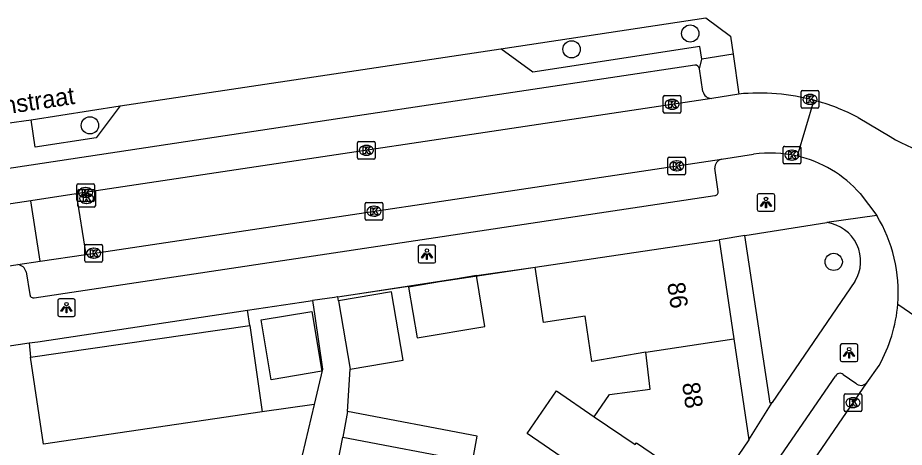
# Model space of a CAD drawing. Extents: x 159280 to 160375, y 384531 to 385872.
# Drawn here: x 159824.7 to 159875.1, y 384897 to 384921.4 of the extents above; entities that cross this region are included whole.
import ezdxf

# ---------------------------------------------------------------- set-up
doc = ezdxf.new("R2010")
doc.units = 0
for name, color, linetype in [('IMGEO_Boom', 7, 'Continuous'), ('IMGEO_Haag', 7, 'Continuous'), ('IMGEO_Kolk', 7, 'Continuous'), ('IMGEO_Lichtpunt', 7, 'Continuous'), ('IMGEO_Muur', 7, 'Continuous'), ('IMGEO_Openbare_ruimte_label', 7, 'Continuous'), ('IMGEO_Pand', 7, 'Continuous'), ('IMGEO_Pand_nummerreeks', 7, 'Continuous'), ('IMGEO_Parkeervlak_open', 7, 'Continuous'), ('IMGEO_Rijbaan_lokaal_open', 7, 'Continuous'), ('IMGEO_Voetpad_open', 7, 'Continuous')]:
    doc.layers.add(name, color=color, linetype=linetype)

msp = doc.modelspace()

# ---------------------------------------------------------------- linework, layer by layer
at = {"layer": 'IMGEO_Boom'}
for centre in [(159862.906, 384920.484), (159856.17, 384919.589), (159828.826, 384915.274), (159871.051, 384907.532)]:
    msp.add_circle(centre, 0.489, dxfattribs=at)
at = {"layer": 'IMGEO_Haag'}
msp.add_lwpolyline([(159865.34, 384919.305), (159863.557, 384919.029)], dxfattribs=at)
at = {"layer": 'IMGEO_Kolk'}
for p, q in [((159861.375, 384916.043), (159861.375, 384916.895)), ((159861.45, 384916.969), (159862.302, 384916.969)), ((159862.376, 384916.895), (159862.376, 384916.043)), ((159869.203, 384916.321), (159869.203, 384917.173)), ((159869.278, 384917.247), (159870.13, 384917.247)), ((159869.691, 384917.027), (159869.716, 384917.027)), ((159870.204, 384917.173), (159870.204, 384916.321)), ((159861.863, 384916.749), (159861.888, 384916.749)), ((159869.714, 384916.467), (159869.689, 384916.467)), ((159862.302, 384915.969), (159861.45, 384915.969)), ((159861.886, 384916.189), (159861.861, 384916.189)), ((159870.13, 384916.247), (159869.278, 384916.247)), ((159844.094, 384914.359), (159844.946, 384914.359)), ((159844.019, 384913.433), (159844.019, 384914.285)), ((159844.507, 384914.139), (159844.532, 384914.139)), ((159845.02, 384914.285), (159845.02, 384913.433)), ((159868.179, 384913.159), (159868.179, 384914.011)), ((159868.254, 384914.085), (159869.106, 384914.085)), ((159868.667, 384913.865), (159868.692, 384913.865)), ((159869.18, 384914.011), (159869.18, 384913.159)), ((159844.946, 384913.359), (159844.094, 384913.359)), ((159844.53, 384913.579), (159844.505, 384913.579)), ((159861.638, 384912.551), (159861.638, 384913.403)), ((159861.713, 384913.477), (159862.565, 384913.477)), ((159862.639, 384913.403), (159862.639, 384912.551)), ((159862.126, 384913.257), (159862.151, 384913.257)), ((159869.106, 384913.085), (159868.254, 384913.085)), ((159868.69, 384913.305), (159868.665, 384913.305)), ((159862.565, 384912.477), (159861.713, 384912.477)), ((159862.149, 384912.697), (159862.124, 384912.697)), ((159828.08, 384911.037), (159828.08, 384911.889)), ((159828.155, 384911.963), (159829.007, 384911.963)), ((159829.081, 384911.889), (159829.081, 384911.037)), ((159828.133, 384910.704), (159828.133, 384911.556)), ((159828.208, 384911.63), (159829.06, 384911.63)), ((159828.568, 384911.743), (159828.593, 384911.743)), ((159828.621, 384911.41), (159828.646, 384911.41)), ((159829.134, 384911.556), (159829.134, 384910.704)), ((159829.007, 384910.963), (159828.155, 384910.963)), ((159828.591, 384911.183), (159828.566, 384911.183)), ((159828.644, 384910.85), (159828.619, 384910.85)), ((159844.45, 384909.978), (159844.45, 384910.83)), ((159844.525, 384910.904), (159845.377, 384910.904)), ((159845.451, 384910.83), (159845.451, 384909.978)), ((159829.06, 384910.63), (159828.208, 384910.63)), ((159844.938, 384910.684), (159844.963, 384910.684)), ((159845.377, 384909.904), (159844.525, 384909.904)), ((159844.961, 384910.124), (159844.936, 384910.124)), ((159828.54, 384907.597), (159828.54, 384908.449)), ((159828.615, 384908.523), (159829.467, 384908.523)), ((159829.541, 384908.449), (159829.541, 384907.597)), ((159829.028, 384908.303), (159829.053, 384908.303)), ((159829.467, 384907.523), (159828.615, 384907.523)), ((159829.051, 384907.743), (159829.026, 384907.743)), ((159871.645, 384899.121), (159871.645, 384899.973)), ((159871.72, 384900.047), (159872.572, 384900.047)), ((159872.133, 384899.827), (159872.158, 384899.827)), ((159872.646, 384899.973), (159872.646, 384899.121)), ((159872.156, 384899.267), (159872.131, 384899.267)), ((159872.572, 384899.047), (159871.72, 384899.047))]:
    msp.add_line(p, q, dxfattribs=at)
for points in [[(159861.375, 384916.043), (159861.375, 384916.895)], [(159861.45, 384916.969), (159862.302, 384916.969)], [(159862.376, 384916.895), (159862.376, 384916.043)], [(159869.203, 384916.321), (159869.203, 384917.173)], [(159869.278, 384917.247), (159870.13, 384917.247)], [(159869.524, 384916.947), (159869.647, 384916.947), (159869.647, 384916.796), (159869.777, 384916.947), (159869.941, 384916.947), (159869.795, 384916.796), (159869.948, 384916.547), (159869.796, 384916.547), (159869.711, 384916.711), (159869.647, 384916.644), (159869.647, 384916.547), (159869.524, 384916.547), (159869.524, 384916.947)], [(159870.204, 384917.173), (159870.204, 384916.321)], [(159861.696, 384916.669), (159861.819, 384916.669), (159861.819, 384916.518), (159861.949, 384916.669), (159862.113, 384916.669), (159861.967, 384916.518), (159862.12, 384916.269), (159861.968, 384916.269), (159861.883, 384916.433), (159861.819, 384916.366), (159861.819, 384916.269), (159861.696, 384916.269), (159861.696, 384916.669)], [(159862.302, 384915.969), (159861.45, 384915.969)], [(159870.13, 384916.247), (159869.278, 384916.247)], [(159844.094, 384914.359), (159844.946, 384914.359)], [(159844.019, 384913.433), (159844.019, 384914.285)], [(159844.34, 384914.059), (159844.463, 384914.059), (159844.463, 384913.908), (159844.593, 384914.059), (159844.757, 384914.059), (159844.611, 384913.908), (159844.764, 384913.659), (159844.612, 384913.659), (159844.527, 384913.823), (159844.463, 384913.756), (159844.463, 384913.659), (159844.34, 384913.659), (159844.34, 384914.059)], [(159845.02, 384914.285), (159845.02, 384913.433)], [(159868.179, 384913.159), (159868.179, 384914.011)], [(159868.254, 384914.085), (159869.106, 384914.085)], [(159869.18, 384914.011), (159869.18, 384913.159)], [(159844.946, 384913.359), (159844.094, 384913.359)], [(159861.638, 384912.551), (159861.638, 384913.403)], [(159861.713, 384913.477), (159862.565, 384913.477)], [(159862.639, 384913.403), (159862.639, 384912.551)], [(159868.5, 384913.785), (159868.623, 384913.785), (159868.623, 384913.634), (159868.753, 384913.785), (159868.917, 384913.785), (159868.771, 384913.634), (159868.924, 384913.385), (159868.772, 384913.385), (159868.687, 384913.549), (159868.623, 384913.482), (159868.623, 384913.385), (159868.5, 384913.385), (159868.5, 384913.785)], [(159861.959, 384913.177), (159862.082, 384913.177), (159862.082, 384913.026), (159862.212, 384913.177), (159862.376, 384913.177), (159862.23, 384913.026), (159862.383, 384912.777), (159862.231, 384912.777), (159862.146, 384912.941), (159862.082, 384912.874), (159862.082, 384912.777), (159861.959, 384912.777), (159861.959, 384913.177)], [(159869.106, 384913.085), (159868.254, 384913.085)], [(159862.565, 384912.477), (159861.713, 384912.477)], [(159828.08, 384911.037), (159828.08, 384911.889)], [(159828.155, 384911.963), (159829.007, 384911.963)], [(159829.081, 384911.889), (159829.081, 384911.037)], [(159828.133, 384910.704), (159828.133, 384911.556)], [(159828.208, 384911.63), (159829.06, 384911.63)], [(159828.401, 384911.663), (159828.524, 384911.663), (159828.524, 384911.512), (159828.654, 384911.663), (159828.818, 384911.663), (159828.672, 384911.512), (159828.825, 384911.263), (159828.673, 384911.263), (159828.588, 384911.427), (159828.524, 384911.36), (159828.524, 384911.263), (159828.401, 384911.263), (159828.401, 384911.663)], [(159828.454, 384911.33), (159828.577, 384911.33), (159828.577, 384911.179), (159828.707, 384911.33), (159828.871, 384911.33), (159828.725, 384911.179), (159828.878, 384910.93), (159828.726, 384910.93), (159828.641, 384911.094), (159828.577, 384911.027), (159828.577, 384910.93), (159828.454, 384910.93), (159828.454, 384911.33)], [(159829.134, 384911.556), (159829.134, 384910.704)], [(159829.007, 384910.963), (159828.155, 384910.963)], [(159844.45, 384909.978), (159844.45, 384910.83)], [(159844.525, 384910.904), (159845.377, 384910.904)], [(159845.451, 384910.83), (159845.451, 384909.978)], [(159829.06, 384910.63), (159828.208, 384910.63)], [(159844.771, 384910.604), (159844.894, 384910.604), (159844.894, 384910.453), (159845.024, 384910.604), (159845.188, 384910.604), (159845.042, 384910.453), (159845.195, 384910.204), (159845.043, 384910.204), (159844.958, 384910.368), (159844.894, 384910.301), (159844.894, 384910.204), (159844.771, 384910.204), (159844.771, 384910.604)], [(159845.377, 384909.904), (159844.525, 384909.904)], [(159828.54, 384907.597), (159828.54, 384908.449)], [(159828.615, 384908.523), (159829.467, 384908.523)], [(159829.541, 384908.449), (159829.541, 384907.597)], [(159828.861, 384908.223), (159828.984, 384908.223), (159828.984, 384908.072), (159829.114, 384908.223), (159829.278, 384908.223), (159829.132, 384908.072), (159829.285, 384907.823), (159829.133, 384907.823), (159829.048, 384907.987), (159828.984, 384907.92), (159828.984, 384907.823), (159828.861, 384907.823), (159828.861, 384908.223)], [(159829.467, 384907.523), (159828.615, 384907.523)], [(159871.645, 384899.121), (159871.645, 384899.973)], [(159871.72, 384900.047), (159872.572, 384900.047)], [(159872.646, 384899.973), (159872.646, 384899.121)], [(159871.966, 384899.747), (159872.089, 384899.747), (159872.089, 384899.596), (159872.219, 384899.747), (159872.383, 384899.747), (159872.237, 384899.596), (159872.39, 384899.347), (159872.238, 384899.347), (159872.153, 384899.511), (159872.089, 384899.444), (159872.089, 384899.347), (159871.966, 384899.347), (159871.966, 384899.747)], [(159872.572, 384899.047), (159871.72, 384899.047)]]:
    msp.add_lwpolyline(points, dxfattribs=at)
for centre, start, end in [((159861.452, 384916.893), 91.552, 178.448), ((159861.452, 384916.893), 91.552, 178.448), ((159862.3, 384916.893), 1.552, 88.448), ((159862.3, 384916.893), 1.552, 88.448), ((159869.28, 384917.171), 91.552, 178.448), ((159869.28, 384917.171), 91.552, 178.448), ((159870.128, 384917.171), 1.552, 88.448), ((159870.128, 384917.171), 1.552, 88.448), ((159861.452, 384916.045), 181.552, 268.448), ((159861.452, 384916.045), 181.552, 268.448), ((159862.3, 384916.045), 271.552, 358.448), ((159862.3, 384916.045), 271.552, 358.448), ((159869.28, 384916.323), 181.552, 268.448), ((159869.28, 384916.323), 181.552, 268.448), ((159870.128, 384916.323), 271.552, 358.448), ((159870.128, 384916.323), 271.552, 358.448), ((159844.096, 384914.283), 91.552, 178.448), ((159844.096, 384914.283), 91.552, 178.448), ((159844.944, 384914.283), 1.552, 88.448), ((159844.944, 384914.283), 1.552, 88.448), ((159868.256, 384914.009), 91.552, 178.448), ((159868.256, 384914.009), 91.552, 178.448), ((159869.104, 384914.009), 1.552, 88.448), ((159869.104, 384914.009), 1.552, 88.448), ((159844.096, 384913.435), 181.552, 268.448), ((159844.096, 384913.435), 181.552, 268.448), ((159844.944, 384913.435), 271.552, 358.448), ((159844.944, 384913.435), 271.552, 358.448), ((159861.715, 384913.401), 91.552, 178.448), ((159861.715, 384913.401), 91.552, 178.448), ((159862.563, 384913.401), 1.552, 88.448), ((159862.563, 384913.401), 1.552, 88.448), ((159868.256, 384913.161), 181.552, 268.448), ((159868.256, 384913.161), 181.552, 268.448), ((159869.104, 384913.161), 271.552, 358.448), ((159869.104, 384913.161), 271.552, 358.448), ((159861.715, 384912.553), 181.552, 268.448), ((159861.715, 384912.553), 181.552, 268.448), ((159862.563, 384912.553), 271.552, 358.448), ((159862.563, 384912.553), 271.552, 358.448), ((159828.157, 384911.887), 91.552, 178.448), ((159828.157, 384911.887), 91.552, 178.448), ((159829.005, 384911.887), 1.552, 88.448), ((159829.005, 384911.887), 1.552, 88.448), ((159828.21, 384911.554), 91.552, 178.448), ((159828.21, 384911.554), 91.552, 178.448), ((159829.058, 384911.554), 1.552, 88.448), ((159829.058, 384911.554), 1.552, 88.448), ((159828.157, 384911.039), 181.552, 268.448), ((159828.157, 384911.039), 181.552, 268.448), ((159829.005, 384911.039), 271.552, 358.448), ((159829.005, 384911.039), 271.552, 358.448), ((159844.527, 384910.828), 91.552, 178.448), ((159844.527, 384910.828), 91.552, 178.448), ((159845.375, 384910.828), 1.552, 88.448), ((159845.375, 384910.828), 1.552, 88.448), ((159828.21, 384910.706), 181.552, 268.448), ((159828.21, 384910.706), 181.552, 268.448), ((159829.058, 384910.706), 271.552, 358.448), ((159829.058, 384910.706), 271.552, 358.448), ((159844.527, 384909.98), 181.552, 268.448), ((159844.527, 384909.98), 181.552, 268.448), ((159845.375, 384909.98), 271.552, 358.448), ((159845.375, 384909.98), 271.552, 358.448), ((159828.617, 384908.447), 91.552, 178.448), ((159828.617, 384908.447), 91.552, 178.448), ((159829.465, 384908.447), 1.552, 88.448), ((159829.465, 384908.447), 1.552, 88.448), ((159828.617, 384907.599), 181.552, 268.448), ((159828.617, 384907.599), 181.552, 268.448), ((159829.465, 384907.599), 271.552, 358.448), ((159829.465, 384907.599), 271.552, 358.448), ((159871.722, 384899.971), 91.552, 178.448), ((159871.722, 384899.971), 91.552, 178.448), ((159872.57, 384899.971), 1.552, 88.448), ((159872.57, 384899.971), 1.552, 88.448), ((159871.722, 384899.123), 181.552, 268.448), ((159871.722, 384899.123), 181.552, 268.448), ((159872.57, 384899.123), 271.552, 358.448), ((159872.57, 384899.123), 271.552, 358.448)]:
    msp.add_arc(centre, 0.0765, start, end, dxfattribs=at)
for centre, major_axis, ratio, start_param, end_param in [((159869.69, 384916.747), (-0.387, 0.002), 0.722429, 4.712389, 7.853982), ((159869.715, 384916.747), (-0.39, 0.002), 0.717154, 1.570796, 4.712389), ((159861.862, 384916.469), (-0.387, 0.002), 0.722429, 4.712389, 7.853982), ((159861.887, 384916.469), (-0.39, 0.002), 0.717154, 1.570796, 4.712389), ((159844.506, 384913.859), (-0.387, 0.002), 0.722429, 4.712389, 7.853982), ((159844.531, 384913.859), (-0.39, 0.002), 0.717154, 1.570796, 4.712389), ((159868.666, 384913.585), (-0.387, 0.002), 0.722429, 4.712389, 7.853982), ((159868.691, 384913.585), (-0.39, 0.002), 0.717154, 1.570796, 4.712389), ((159862.125, 384912.977), (-0.387, 0.002), 0.722429, 4.712389, 7.853982), ((159862.15, 384912.977), (-0.39, 0.002), 0.717154, 1.570796, 4.712389), ((159828.567, 384911.463), (-0.387, 0.002), 0.722429, 4.712389, 7.853982), ((159828.62, 384911.13), (-0.387, 0.002), 0.722429, 4.712389, 7.853982), ((159828.592, 384911.463), (-0.39, 0.002), 0.717154, 1.570796, 4.712389), ((159828.645, 384911.13), (-0.39, 0.002), 0.717154, 1.570796, 4.712389), ((159844.937, 384910.404), (-0.387, 0.002), 0.722429, 4.712389, 7.853982), ((159844.962, 384910.404), (-0.39, 0.002), 0.717154, 1.570796, 4.712389), ((159829.027, 384908.023), (-0.387, 0.002), 0.722429, 4.712389, 7.853982), ((159829.052, 384908.023), (-0.39, 0.002), 0.717154, 1.570796, 4.712389), ((159872.132, 384899.547), (-0.387, 0.002), 0.722429, 4.712389, 7.853982), ((159872.157, 384899.547), (-0.39, 0.002), 0.717154, 1.570796, 4.712389)]:
    msp.add_ellipse(centre, major_axis=major_axis, ratio=ratio, start_param=start_param, end_param=end_param, dxfattribs=at)
at = {"layer": 'IMGEO_Lichtpunt'}
for p, q in [((159867.612, 384911.396), (159866.804, 384911.396)), ((159867.612, 384911.396), (159866.804, 384911.396)), ((159866.71, 384911.301), (159866.71, 384910.494)), ((159866.71, 384911.301), (159866.71, 384910.494)), ((159867.706, 384910.494), (159867.706, 384911.301)), ((159867.706, 384910.494), (159867.706, 384911.301)), ((159866.804, 384910.4), (159867.612, 384910.4)), ((159866.804, 384910.4), (159867.612, 384910.4)), ((159847.457, 384908.376), (159847.457, 384907.569)), ((159847.457, 384908.376), (159847.457, 384907.569)), ((159848.359, 384908.471), (159847.551, 384908.471)), ((159848.359, 384908.471), (159847.551, 384908.471)), ((159848.453, 384907.569), (159848.453, 384908.376)), ((159848.453, 384907.569), (159848.453, 384908.376)), ((159847.551, 384907.475), (159848.359, 384907.475)), ((159847.551, 384907.475), (159848.359, 384907.475)), ((159826.996, 384905.34), (159826.996, 384904.533)), ((159826.996, 384905.34), (159826.996, 384904.533)), ((159827.898, 384905.435), (159827.09, 384905.435)), ((159827.898, 384905.435), (159827.09, 384905.435)), ((159827.992, 384904.533), (159827.992, 384905.34)), ((159827.992, 384904.533), (159827.992, 384905.34)), ((159827.09, 384904.439), (159827.898, 384904.439)), ((159827.09, 384904.439), (159827.898, 384904.439)), ((159871.425, 384902.784), (159871.425, 384901.977)), ((159871.425, 384902.784), (159871.425, 384901.977)), ((159872.327, 384902.879), (159871.519, 384902.879)), ((159872.327, 384902.879), (159871.519, 384902.879)), ((159872.421, 384901.977), (159872.421, 384902.784)), ((159872.421, 384901.977), (159872.421, 384902.784)), ((159871.519, 384901.883), (159872.327, 384901.883)), ((159871.519, 384901.883), (159872.327, 384901.883))]:
    msp.add_line(p, q, dxfattribs=at)
for points in [[(159867.084, 384910.965), (159867.123, 384910.937), (159866.935, 384910.675), (159866.897, 384910.702), (159867.084, 384910.965)], [(159867.186, 384910.917), (159867.233, 384910.917), (159867.233, 384910.595), (159867.186, 384910.595), (159867.186, 384910.917)], [(159867.296, 384910.937), (159867.334, 384910.964), (159867.521, 384910.702), (159867.482, 384910.674), (159867.296, 384910.937)], [(159847.831, 384908.04), (159847.87, 384908.012), (159847.682, 384907.75), (159847.644, 384907.777), (159847.831, 384908.04)], [(159847.933, 384907.992), (159847.98, 384907.992), (159847.98, 384907.67), (159847.933, 384907.67), (159847.933, 384907.992)], [(159848.043, 384908.012), (159848.081, 384908.039), (159848.268, 384907.777), (159848.229, 384907.749), (159848.043, 384908.012)], [(159827.37, 384905.004), (159827.409, 384904.976), (159827.221, 384904.714), (159827.183, 384904.741), (159827.37, 384905.004)], [(159827.472, 384904.956), (159827.519, 384904.956), (159827.519, 384904.634), (159827.472, 384904.634), (159827.472, 384904.956)], [(159827.582, 384904.976), (159827.62, 384905.003), (159827.807, 384904.741), (159827.768, 384904.713), (159827.582, 384904.976)], [(159871.799, 384902.448), (159871.838, 384902.42), (159871.65, 384902.158), (159871.612, 384902.185), (159871.799, 384902.448)], [(159871.901, 384902.4), (159871.948, 384902.4), (159871.948, 384902.078), (159871.901, 384902.078), (159871.901, 384902.4)], [(159872.011, 384902.42), (159872.049, 384902.447), (159872.236, 384902.185), (159872.197, 384902.157), (159872.011, 384902.42)]]:
    msp.add_lwpolyline(points, dxfattribs=at)
for centre in [(159867.209, 384911.099), (159847.956, 384908.174), (159827.495, 384905.138), (159871.924, 384902.582)]:
    msp.add_circle(centre, 0.0994, dxfattribs=at)
for centre, start, end in [((159866.804, 384911.301), 90, 180), ((159866.804, 384911.301), 90, 180), ((159867.612, 384911.301), 0, 90), ((159867.612, 384911.301), 0, 90), ((159866.804, 384910.494), 180, 270), ((159866.804, 384910.494), 180, 270), ((159867.612, 384910.494), 270, 0), ((159867.612, 384910.494), 270, 360), ((159847.551, 384908.376), 90, 180), ((159847.551, 384908.376), 90, 180), ((159848.359, 384908.376), 0, 90), ((159848.359, 384908.376), 0, 90), ((159847.551, 384907.569), 180, 270), ((159847.551, 384907.569), 180, 270), ((159848.359, 384907.569), 270, 0), ((159848.359, 384907.569), 270, 360), ((159827.09, 384905.34), 90, 180), ((159827.09, 384905.34), 90, 180), ((159827.898, 384905.34), 0, 90), ((159827.898, 384905.34), 0, 90), ((159827.09, 384904.533), 180, 270), ((159827.09, 384904.533), 180, 270), ((159827.898, 384904.533), 270, 0), ((159827.898, 384904.533), 270, 360), ((159871.519, 384902.784), 90, 180), ((159871.519, 384902.784), 90, 180), ((159872.327, 384902.784), 0, 90), ((159872.327, 384902.784), 0, 90), ((159871.519, 384901.977), 180, 270), ((159871.519, 384901.977), 180, 270), ((159872.327, 384901.977), 270, 0), ((159872.327, 384901.977), 270, 360)]:
    msp.add_arc(centre, 0.0946, start, end, dxfattribs=at)
at = {"layer": 'IMGEO_Muur'}
msp.add_lwpolyline([(159842.883, 384905.542), (159854.105, 384907.239)], dxfattribs=at)
at = {"layer": 'IMGEO_Pand'}
for points in [[(159854.105, 384907.239), (159864.542, 384908.773)], [(159864.542, 384908.773), (159865.376, 384903.166)], [(159860.376, 384902.42), (159857.327, 384901.889), (159856.945, 384904.451), (159854.568, 384904.097), (159854.105, 384907.239)], [(159850.765, 384906.751), (159846.908, 384906.098), (159847.396, 384903.217), (159851.253, 384903.87), (159850.765, 384906.751)], [(159843.591, 384901.442), (159846.602, 384901.952), (159845.945, 384905.832), (159842.933, 384905.322)], [(159842.933, 384905.322), (159843.591, 384901.442)], [(159838.544, 384904.238), (159841.425, 384904.726), (159842, 384901.333), (159839.118, 384900.845), (159838.544, 384904.238)], [(159860.376, 384902.42), (159865.376, 384903.166)], [(159865.376, 384903.166), (159866.228, 384897.439)], [(159857.456, 384898.753), (159858.315, 384900.016), (159860.639, 384900.304), (159860.376, 384902.42)], [(159854.078, 384894.268), (159855.587, 384896.483), (159853.657, 384897.798), (159855.306, 384900.218), (159857.456, 384898.753)], [(159843.457, 384899.052), (159843.178, 384897.596)], [(159850.535, 384896.191), (159850.813, 384897.646), (159843.457, 384899.052)], [(159857.456, 384898.753), (159859.775, 384897.173), (159859.846, 384897.277), (159864.13, 384894.359)], [(159842.9, 384896.141), (159843.178, 384897.596)], [(159843.178, 384897.596), (159850.535, 384896.191)], [(159866.228, 384897.439), (159864.13, 384894.359)]]:
    msp.add_lwpolyline(points, dxfattribs=at)
at = {"layer": 'IMGEO_Parkeervlak_open'}
for points in [[(159863.626, 384917.194), (159863.432, 384918.475)], [(159825.454, 384902.133), (159837.899, 384903.928)]]:
    msp.add_lwpolyline(points, dxfattribs=at)
msp.add_arc((159864.103, 384917.294), 0.487, 191.8199, 272.5893, dxfattribs=at)
at = {"layer": 'IMGEO_Rijbaan_lokaal_open'}
for points in [[(159865.659, 384917.05), (159864.125, 384916.807)], [(159864.125, 384916.807), (159828.051, 384911.384)], [(159869.928, 384916.698), (159868.968, 384913.533)], [(159872.431, 384915.719), (159874.25, 384914.647)], [(159828.584, 384907.954), (159864.675, 384913.357)], [(159864.675, 384913.357), (159866.501, 384913.634)], [(159828.051, 384911.384), (159825.463, 384910.995)], [(159828.051, 384911.384), (159828.584, 384907.954)], [(159872.55, 384911.403), (159873.494, 384910.171)], [(159825.463, 384910.995), (159801.309, 384907.363)], [(159825.995, 384907.567), (159825.463, 384910.995)], [(159825.995, 384907.567), (159828.584, 384907.954)], [(159819.621, 384906.592), (159824.727, 384907.377)], [(159824.727, 384907.377), (159825.995, 384907.567)], [(159874.688, 384905.142), (159879.386, 384901.926)], [(159819.36, 384902.035), (159825.377, 384902.95)], [(159825.377, 384902.95), (159825.454, 384902.133)], [(159838.611, 384899.034), (159826.187, 384897.193), (159825.454, 384902.133)], [(159872.922, 384900.679), (159873.627, 384901.661)], [(159853.991, 384872.729), (159864.145, 384887.869), (159872.922, 384900.679)], [(159841.555, 384899.435), (159840.533, 384895.132), (159839.504, 384893.107), (159834.289, 384892.315)], [(159841.555, 384899.435), (159838.611, 384899.034)]]:
    msp.add_lwpolyline(points, dxfattribs=at)
for centre, radius, start, end in [((159866.818, 384905.041), 12.065, 75.0607, 95.5119), ((159866.847, 384905.132), 11.97, 62.1919, 75.0841), ((159878.093, 384920.645), 7.123, 237.3492, 325.0498), ((159867.462, 384906.937), 6.766, 77.1417, 98.1695), ((159867.463, 384906.924), 6.778, 41.3581, 77.1671), ((159866.159, 384905.773), 8.552, 355.7664, 30.9457), ((159866.345, 384905.783), 8.367, 330.489, 355.6088)]:
    msp.add_arc(centre, radius, start, end, dxfattribs=at)
at = {"layer": 'IMGEO_Voetpad_open'}
for points in [[(159852.152, 384919.622), (159863.783, 384921.378), (159865.194, 384920.335), (159865.34, 384919.305)], [(159830.534, 384916.379), (159852.152, 384919.622)], [(159863.557, 384919.029), (159863.441, 384919.748), (159853.976, 384918.285), (159852.152, 384919.622)], [(159863.432, 384918.475), (159863.557, 384919.029)], [(159865.34, 384919.305), (159865.659, 384917.05)], [(159863.162, 384918.694), (159844.016, 384915.81), (159801.678, 384909.433)], [(159825.49, 384915.597), (159830.534, 384916.379)], [(159830.534, 384916.379), (159829.186, 384914.57), (159825.714, 384914.039), (159825.49, 384915.597)], [(159824.099, 384915.408), (159825.49, 384915.597)], [(159864.486, 384911.528), (159864.305, 384912.843)], [(159825.668, 384905.493), (159864.301, 384911.295)], [(159873.494, 384910.171), (159870.658, 384909.761)], [(159866.011, 384909.019), (159870.658, 384909.761)], [(159866.011, 384909.019), (159864.542, 384908.773)], [(159867.556, 384899.554), (159867.439, 384899.516), (159866.011, 384909.019)], [(159825.203, 384906.965), (159825.42, 384905.678)], [(159850.765, 384906.751), (159854.105, 384907.239)], [(159842.895, 384905.544), (159850.765, 384906.751)], [(159872.248, 384906.412), (159867.556, 384899.554)], [(159837.771, 384904.785), (159840.835, 384905.243), (159841.464, 384905.335)], [(159842.895, 384905.544), (159842.883, 384905.542), (159842.713, 384905.517), (159841.464, 384905.335)], [(159841.464, 384905.335), (159841.591, 384904.46), (159842.032, 384901.442), (159841.787, 384900.411), (159841.555, 384899.435)], [(159842.933, 384905.322), (159842.895, 384905.544)], [(159825.377, 384902.95), (159825.86, 384903.003), (159837.771, 384904.785)], [(159837.899, 384903.928), (159837.771, 384904.785)], [(159837.899, 384903.928), (159838.611, 384899.034)], [(159843.457, 384899.052), (159843.591, 384901.442)], [(159854.183, 384876.035), (159862.663, 384888.7), (159871.149, 384901.051)], [(159871.581, 384901.139), (159872.305, 384900.658)], [(159866.228, 384897.439), (159867.556, 384899.554)]]:
    msp.add_lwpolyline(points, dxfattribs=at)
for centre, radius, start, end in [((159863.175, 384918.434), 0.261, 9.1097, 92.7985), ((159864.798, 384912.878), 0.495, 104.4547, 184.0493), ((159864.3, 384911.486), 0.191, 270.4356, 12.6658), ((159870.376, 384907.575), 2.204, 328.1514, 82.6424), ((159824.666, 384906.825), 0.555, 14.5898, 83.6548), ((159825.616, 384905.682), 0.196, 181.3093, 285.2472), ((159871.396, 384900.945), 0.268, 46.2829, 156.7448), ((159872.604, 384900.943), 0.413, 223.5965, 320.3022)]:
    msp.add_arc(centre, radius, start, end, dxfattribs=at)

# ---------------------------------------------------------------- texts
at = {"layer": 'IMGEO_Openbare_ruimte_label'}
msp.add_text('2e Franklinstraat', height=1, rotation=8.5676, dxfattribs=at).set_placement((159818.171, 384915.011))
at = {"layer": 'IMGEO_Pand_nummerreeks'}
for s, p in [('86', (159861.594, 384906.305)), ('88', (159862.437, 384900.635))]:
    msp.add_text(s, height=1, rotation=278.4624, dxfattribs=at).set_placement(p)

doc.saveas('drawing.dxf')
